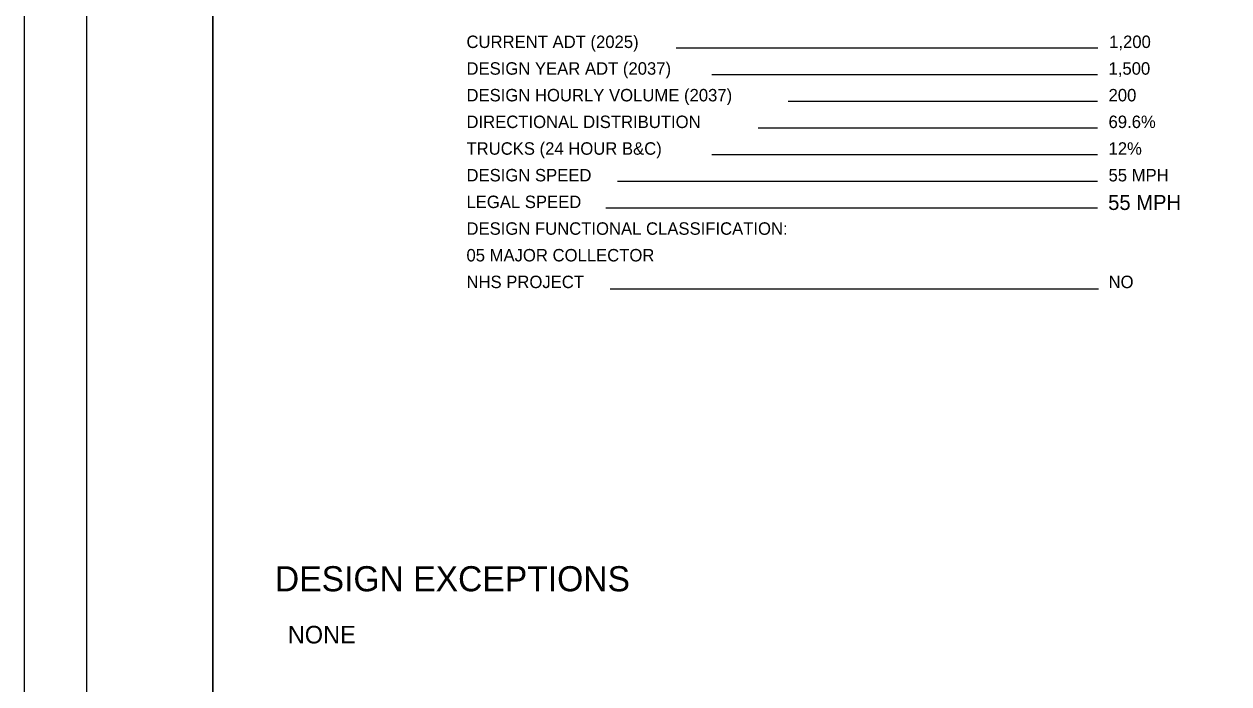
# Model space of a CAD drawing. Extents: x 0 to 34, y 0 to 22.
# Drawn here: x 0 to 9.58, y 5.64 to 10.89 of the extents above; entities that cross this region are included whole.
import ezdxf

# ---------------------------------------------------------------- set-up
doc = ezdxf.new("R2010")
doc.units = 0
for name, color, linetype in [('Default', 7, 'Continuous'), ('SH_Border', 7, 'Continuous'), ('SH_Cut_Line', 7, 'Continuous'), ('SH_Data', 7, 'Continuous'), ('SH_Text', 7, 'Continuous')]:
    doc.layers.add(name, color=color, linetype=linetype)

msp = doc.modelspace()

# ---------------------------------------------------------------- linework, layer by layer
at = {"layer": 'SH_Border'}
for points in [[(0.5, 21.5), (1.5, 21.5), (1.5, 0.5), (0.5, 0.5)], [(1.5, 21.5), (33.5, 21.5), (33.5, 0.5), (1.5, 0.5)]]:
    msp.add_lwpolyline(points, close=True, dxfattribs=at)
at = {"layer": 'SH_Cut_Line'}
msp.add_lwpolyline([(0, 0), (34, 0), (34, 22), (0, 22)], close=True, dxfattribs=at)
at = {"layer": 'SH_Data'}
for p, q in [((8.5391, 10.6974), (5.1861, 10.6974)), ((8.5342, 10.4851), (5.4674, 10.4851)), ((8.5342, 10.2728), (6.0763, 10.2728)), ((8.5342, 10.0606), (5.8375, 10.0606)), ((8.5342, 9.8483), (5.4683, 9.8483)), ((8.5342, 9.6361), (4.7193, 9.6361)), ((8.5342, 9.4238), (4.627, 9.4238)), ((8.5445, 8.7792), (4.6593, 8.7792))]:
    msp.add_line(p, q, dxfattribs=at)

# ---------------------------------------------------------------- texts
at = {"layer": 'Default'}
for s, height, p in [('55 MPH', 0.12, (8.6201, 9.4087)), ('NONE', 0.14, (2.0965, 5.9596))]:
    msp.add_text(s, height=height, dxfattribs=at).set_placement(p)
at = {"layer": 'SH_Text'}
for s, height, p in [('CURRENT ADT (2025)', 0.099056, (3.5176, 10.6974)), ('1,200', 0.09906, (8.628, 10.6974)), ('DESIGN YEAR ADT (2037)', 0.099056, (3.5176, 10.4851)), ('1,500', 0.09906, (8.6231, 10.4851)), ('DESIGN HOURLY VOLUME (2037)', 0.099056, (3.5176, 10.2728)), ('200', 0.09906, (8.6231, 10.2728)), ('DIRECTIONAL DISTRIBUTION', 0.099056, (3.5176, 10.0606)), ('69.6%', 0.09906, (8.6231, 10.0606)), ('TRUCKS (24 HOUR B&C)', 0.099056, (3.5176, 9.8483)), ('12%', 0.09906, (8.6231, 9.8483)), ('DESIGN SPEED', 0.099056, (3.5176, 9.6361)), ('55 MPH', 0.09906, (8.6231, 9.6361)), ('LEGAL SPEED', 0.099056, (3.5176, 9.4238)), ('DESIGN FUNCTIONAL CLASSIFICATION:', 0.099056, (3.5176, 9.2115)), ('05 MAJOR COLLECTOR', 0.099056, (3.5176, 8.9993)), ('NHS PROJECT', 0.099056, (3.5176, 8.787)), ('NO', 0.09906, (8.6231, 8.787)), ('DESIGN EXCEPTIONS', 0.2, (1.9944, 6.3744))]:
    msp.add_text(s, height=height, dxfattribs=at).set_placement(p)

doc.saveas('drawing.dxf')
